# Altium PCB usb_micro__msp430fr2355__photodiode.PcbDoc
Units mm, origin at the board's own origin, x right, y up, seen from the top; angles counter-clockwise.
Board outline 40 x 21 mm, 2 copper layers (Top, Bottom), stack 0 mm thick; 25 components, 16 nets, 135 pads, 49 vias.
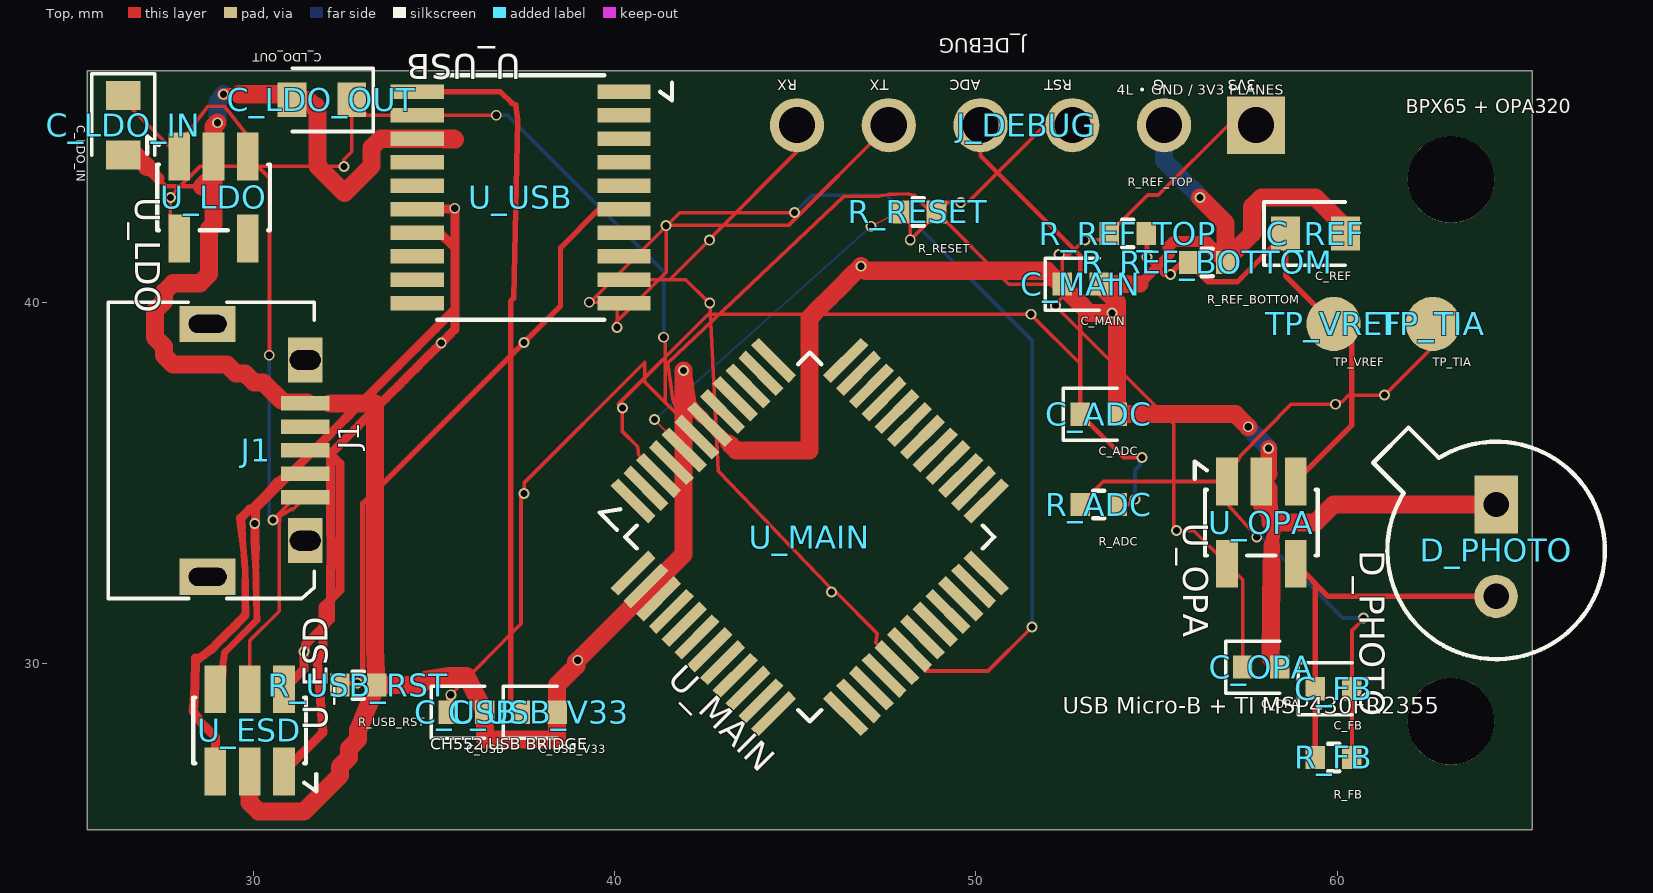
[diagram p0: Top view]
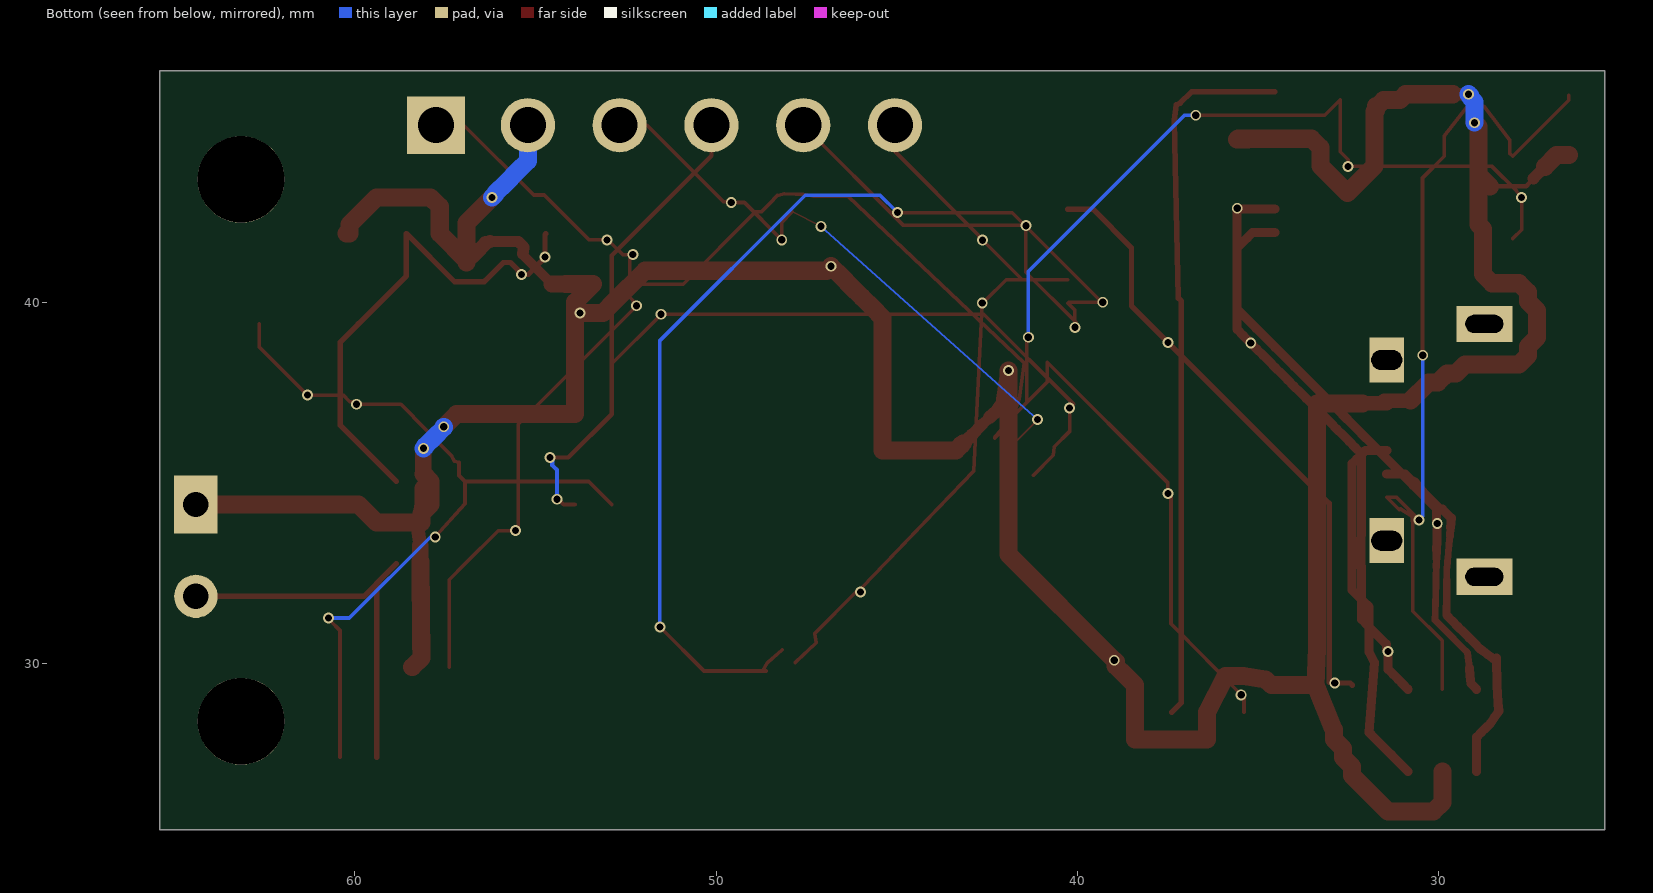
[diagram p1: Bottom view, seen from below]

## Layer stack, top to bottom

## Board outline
25.4,46.4 65.4,46.4 65.4,25.4 25.4,25.4

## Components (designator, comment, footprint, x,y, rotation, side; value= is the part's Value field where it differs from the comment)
C_ADC "" TSCIRCUIT-1.5600x0.6400mm 53.4,36.9 r0 top
C_FB "" TSCIRCUIT-1.5600x0.6400mm 59.9,29.3 r0 top
C_LDO_IN "" TSCIRCUIT-0.9500x2.4500mm 26.4,44.9 r270 top
C_LDO_OUT "" TSCIRCUIT-2.4500x0.9500mm 31.9,45.6 r180 top
C_MAIN "" TSCIRCUIT-1.5600x0.6400mm 52.9,40.5 r0 top
C_OPA "" TSCIRCUIT-1.5600x0.6400mm 57.9,29.9 r0 top
C_REF "" TSCIRCUIT-2.4500x0.9500mm 59.4,41.9 r0 top
C_USB "" TSCIRCUIT-1.5600x0.6400mm 35.9,28.65 r0 top
C_USB_V33 "" TSCIRCUIT-1.5600x0.6400mm 37.9,28.65 r0 top
D_PHOTO "" TSCIRCUIT-1.2000x3.9400mm 64.4,33.23 r270 top
J1 "" TSCIRCUIT-4.1500x8mm 30.037,35.9 r90 top
J_DEBUG "" TSCIRCUIT-14.2000x1.5000mm 51.4,44.9 r180 top
R_ADC "" TSCIRCUIT-1.5600x0.6400mm 53.4,34.4 r0 top
R_FB "" TSCIRCUIT-1.5600x0.6400mm 59.9,27.4 r0 top
R_REF_BOTTOM "" TSCIRCUIT-1.5600x0.6400mm 56.4,41.1 r0 top
R_REF_TOP "" TSCIRCUIT-1.5600x0.6400mm 54.2,41.9 r0 top
R_RESET "" TSCIRCUIT-1.5600x0.6400mm 48.4,42.5 r0 top
R_USB_RST "" TSCIRCUIT-1.5600x0.6400mm 32.9,29.4 r0 top
TP_TIA "" TSCIRCUIT-1.5000x1.5000mm 62.65,39.4 r0 top
TP_VREF "" TSCIRCUIT-1.5000x1.5000mm 59.9,39.4 r0 top
U_ESD "" TSCIRCUIT-2.5000x3.6000mm#1 29.9,28.15 r90 top
U_LDO "" TSCIRCUIT-2.5000x3.6000mm#2 28.9,42.9 r270 top
U_MAIN "" TSCIRCUIT-11.0309x11.0309mm 45.4,33.5 r315 top
U_OPA "" TSCIRCUIT-2.5000x3.6000mm#2 57.9,33.9 r270 top
U_USB "" TSCIRCUIT-7.2000x6.2500mm 37.4,42.9 r180 top

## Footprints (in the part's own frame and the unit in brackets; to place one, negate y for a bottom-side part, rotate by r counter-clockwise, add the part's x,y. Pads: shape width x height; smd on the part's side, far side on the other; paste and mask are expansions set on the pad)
TSCIRCUIT-0.9500x2.4500mm [mm]
  rect 0.8x0.95 smd: 1(-0.825,0) 2(0.825,0)
  silkscreen extent -1.43,-0.87 0.82,0.87
TSCIRCUIT-1.2000x3.9400mm [mm]
  rect 1.6x1.2 hole 0.7: 1(-1.17,0)
  round 1.2 hole 0.7: 2(1.37,0)
  silkscreen extent -3.3,-3.4 3.11,3.01
TSCIRCUIT-1.5000x1.5000mm [mm]
  round 1.5 smd: 1(0,0)
TSCIRCUIT-1.5600x0.6400mm [mm]
  rect 0.54x0.64 smd: 1(-0.51,0) 2(0.51,0)
  silkscreen extent -0.98,-0.72 0.51,0.72
TSCIRCUIT-2.4500x0.9500mm [mm]
  rect 0.8x0.95 smd: 1(-0.825,0) 2(0.825,0)
  silkscreen extent -1.43,-0.87 0.82,0.87
TSCIRCUIT-2.5000x3.6000mm#1 [mm]
  rect 1.325x0.6 smd: 1(-1.137,-0.95) 2(-1.137,0) 3(-1.137,0.95) 4(1.138,0.95) 5(1.138,0) 6(1.138,-0.95)
  silkscreen extent -1.69,-1.84 0.91,1.56
TSCIRCUIT-2.5000x3.6000mm#2 [mm]
  rect 1.325x0.6 smd: 1(-1.137,-0.95) 2(-1.137,0) 3(-1.137,0.95) 4(1.138,0.95) 5(1.138,-0.95)
  silkscreen extent -1.69,-1.84 0.91,1.56
TSCIRCUIT-4.1500x8mm [mm]
  rect 0.4x1.35 smd: 1(-1.301,-1.4) 2(-0.65,-1.4) 3(0,-1.4) 4(0.65,-1.4) 5(1.3,-1.4)
  rect 1.25x0.95 hole 0.55 slot 0.85 at 90 deg: 6(2.5,-1.4) 7(-2.5,-1.4)
  rect 1x1.55 hole 0.5 slot 1.05 at 90 deg: 8(-3.5,1.3) 9(3.5,1.3)
  silkscreen extent -4.1,-1.65 4.1,4.05
TSCIRCUIT-7.2000x6.2500mm [mm]
  rect 1.475x0.4 smd: 1(-2.863,-2.925) 2(-2.863,-2.275) 3(-2.863,-1.625) 4(-2.863,-0.975) 5(-2.863,-0.325) 6(-2.863,0.325) 7(-2.863,0.975) 8(-2.863,1.625) 9(-2.863,2.275) 10(-2.863,2.925) 11(2.862,2.925) 12(2.862,2.275) 13(2.862,1.625) 14(2.862,0.975) 15(2.862,0.325) 16(2.862,-0.325) 17(2.862,-0.975) 18(2.862,-1.625) 19(2.862,-2.275) 20(2.862,-2.925)
  silkscreen extent -4.19,-3.38 2.31,3.38
TSCIRCUIT-11.0309x11.0309mm [mm]
  rect 1.475x0.3 smd: 1(-4.163,-2.75) 2(-4.162,-2.25) 3(-4.163,-1.75) 4(-4.163,-1.25) 5(-4.163,-0.75) 6(-4.162,-0.25) 7(-4.163,0.25) 8(-4.163,0.75) 9(-4.163,1.25) 10(-4.162,1.75) 11(-4.163,2.25) 12(-4.163,2.75) 25(4.162,2.75) 26(4.162,2.25) 27(4.162,1.75) 28(4.162,1.25) 29(4.162,0.75) 30(4.162,0.25) 31(4.162,-0.25) 32(4.162,-0.75) 33(4.162,-1.25) 34(4.162,-1.75) 35(4.162,-2.25) 36(4.162,-2.75)
  rect 0.3x1.475 smd: 13(-2.75,4.162) 14(-2.25,4.163) 15(-1.75,4.162) 16(-1.25,4.162) 17(-0.75,4.162) 18(-0.25,4.163) 19(0.25,4.162) 20(0.75,4.162) 21(1.25,4.162) 22(1.75,4.163) 23(2.25,4.162) 24(2.75,4.162) 37(2.75,-4.162) 38(2.25,-4.162) 39(1.75,-4.162) 40(1.25,-4.162) 41(0.75,-4.162) 42(0.25,-4.162) 43(-0.25,-4.162) 44(-0.75,-4.162) 45(-1.25,-4.162) 46(-1.75,-4.162) 47(-2.25,-4.162) 48(-2.75,-4.162)
  silkscreen extent -4.59,-3.63 3.61,3.61
TSCIRCUIT-14.2000x1.5000mm [mm]
  rect 1.6x1.6 hole 1: 1(-6.35,0)
  round 1.5 hole 1: 2(-3.81,0) 3(-1.27,0) 4(1.27,0) 5(3.81,0) 6(6.35,0)

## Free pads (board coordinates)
  round 2.4 hole 2.4 unplated: NPTH-1(63.15,43.4) NPTH-2(63.15,28.4)

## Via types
v1: diameter 0.3, hole 0.2, Top to Bottom, 49 vias

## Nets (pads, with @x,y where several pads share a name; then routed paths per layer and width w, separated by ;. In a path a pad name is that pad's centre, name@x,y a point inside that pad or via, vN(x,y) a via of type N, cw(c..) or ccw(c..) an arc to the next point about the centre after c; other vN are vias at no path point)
".U_MAIN > .pin5 to .R_RESET > .pin1": J_DEBUG.3 R_RESET.1 U_MAIN.5 | length 16.8
  Top w0.05: v1(41.101,36.75) U_MAIN.5 ; v1(47.1,42.1) R_RESET.1
  Top w0.1: R_RESET.1 48.183,42.207 v1(48.183,41.726) 48.244,41.787 49.216,42.759 v1(49.583,42.759) 49.607,42.783 49.797,42.783 51.915,44.9 J_DEBUG.3
  Bottom w0.05: v1(41.101,36.75) v1(47.1,42.1)
".U_USB > .pin9 to .U_MAIN > .pin32": J_DEBUG.6 U_MAIN.32 U_USB.9 | length 21.8
  Top w0.1: J_DEBUG.6 45.05,44.172 42.735,41.857 42.735,41.83 v1(42.623,41.718) 41.53,40.625 U_USB.9 41.972,40.625 42.531,40.066 42.669,40.066 v1(42.632,39.979) 42.866,35.329 45.956,32.115 45.956,32.028 v1(46.002,31.982) 46.124,31.982 47.274,30.832 47.233,30.573 U_MAIN.32
".U_USB > .pin10 to .U_MAIN > .pin31": J_DEBUG.5 U_MAIN.31 U_USB.10 | length 39.9
  Top w0.1: v1(44.979,42.48) 41.806,42.48 39.313,39.987 v1(39.3,40) 40.238,40 U_USB.10 40.069,39.781 v1(40.069,39.304) 40.038,39.335 40.038,39.445 41.426,40.833 v1(41.426,42.119) 41.432,42.125 41.49,42.125 44.815,42.125 J_DEBUG.5 ; U_MAIN.31 48.573,30.025 48.715,29.797 48.617,29.792 50.337,29.792 51.531,30.986 v1(51.555,31.01)
  Bottom w0.1: v1(44.979,42.48) 44.985,42.486 45.461,42.962 47.534,42.962 51.555,38.941 v1(51.555,31.01)
ADC_IN: C_ADC.1 J_DEBUG.4 R_ADC.2 U_MAIN.3 | length 31.3
  Top w0.1: U_MAIN.3 40.666,35.761 40.638,36 40.217,36.421 v1(40.217,37.073) 40.109,37.181 42.593,39.664 v1(51.522,39.665) 51.577,39.61 51.577,39.606 52.89,38.293 C_ADC.1
  Top w0.12: J_DEBUG.4 50.13,44.052 52.889,41.293 52.889,36.901 C_ADC.1 54.09,35.7 v1(54.6,35.7) ; R_ADC.2 54.221,34.4 54.354,34.534 54.392,34.534 v1(54.406,34.548)
  Bottom w0.12: v1(54.406,34.548) 54.406,35.358 54.539,35.492 54.539,35.639 v1(54.6,35.7)
GND: C_ADC.2 C_LDO_IN.2 C_LDO_OUT.2 C_MAIN.2 C_OPA.2 C_REF.2 C_USB.2 C_USB_V33.2 D_PHOTO.1 J1.5 J_DEBUG.2 R_REF_BOTTOM.2 R_USB_RST.2 U_ESD.2 U_LDO.2 U_MAIN.7 U_OPA.2 U_USB.18 | length 118.9
  Top w0.125: 27.377,43.423 27.575,43.21 28.569,43.21 28.577,43.202
  Top w0.275: 54.539,40.5 54.795,40.756 55.36,41.321 55.36,41.332
  Top w0.3: U_MAIN.7@42.431,36.807 U_MAIN.7
  Top w0.312: 55.36,41.332 55.337,41.4 55.322,41.525 55.478,41.681 55.869,41.681 56.259,41.681
  Top w0.325: 27.057,43.749 27.377,43.423
  Top w0.329: U_MAIN.7 U_MAIN.7@42.922,36.32
  Top w0.35: v1(29.175,45.756) 29.611,45.756 ; 56.259,41.681 56.37,41.64
  Top w0.36: 42.025,37.306 42.228,36.994 U_MAIN.7@42.431,36.807
  Top w0.362: U_MAIN.7@42.922,36.32 U_MAIN.7@43.159,36.102
  Top w0.375: 58.172,34.067 58.244,33.65 58.19,33.266
  Top w0.4: J1.5@30.775,37.275 31.512,37.275 J1.5 J1.5@32.113,37.2 ; U_USB.18 34.563,44.5 U_USB.18@35.275,44.5 ; 56.37,41.64 56.64,41.37 R_REF_BOTTOM.2
  Top w0.45: v1(41.91,38.109) 41.967,37.745 42.025,37.306 ; U_OPA.2@58.103,35.241 v1(58.103,35.955) ; 58.185,32.822 58.19,33.266
  Top w0.475: 43.159,36.102 43.215,36.05 ; 54.163,40.5 54.539,40.5 ; U_OPA.2@58.1,34.484 58.172,34.067
  Top w0.5: C_LDO_IN.2 26.736,44.075 27.057,43.749 ; 28.577,43.202 28.9,43.526 U_LDO.2 ; v1(29.005,44.969) 28.9,44.864 28.9,44.787 28.9,44.412 U_LDO.2 ; 29.611,45.756 30.047,45.756 30.483,45.756 30.919,45.756 C_LDO_OUT.2 31.522,45.6 31.719,45.402 31.741,45.424 31.741,45.309 31.775,45.275 31.775,43.775 32.525,43.025 33.275,43.775 33.275,44.275 33.525,44.525 35.552,44.525 35.577,44.5 35.275,44.5 ; U_ESD.2 29.9,26.15 30.15,25.9 31.4,25.9 32.4,26.9 32.4,27.15 32.65,27.4 32.65,27.65 32.9,27.9 32.9,28.178 32.929,28.206 R_USB_RST.2 ; J1.5@30.775,37.275 30.275,37.775 30.025,37.775 29.775,38.025 29.525,38.025 29.275,38.275 27.775,38.275 27.525,38.525 27.525,38.775 27.275,39.025 27.275,39.775 27.525,40.025 27.525,40.275 27.775,40.525 28.525,40.525 28.775,40.775 28.775,42.025 28.9,42.15 28.9,42.21 28.9,42.667 28.9,43.124 28.9,43.581 U_LDO.2 ; 32.113,37.2 33.365,37.2 33.365,33.368 33.365,32.877 33.365,32.387 33.365,31.897 33.365,31.406 33.365,30.916 33.365,30.425 R_USB_RST.2 ; v1(41.91,38.109) 41.91,33.02 v1(38.981,30.091) 38.939,30.049 38.939,29.931 38.674,29.666 38.41,29.402 38.41,29.026 C_USB_V33.2 38.41,27.9 36.41,27.9 C_USB.2 35.9,29.65 35.4,29.65 34.789,29.561 34.628,29.4 R_USB_RST.2 ; 43.215,36.05 43.358,35.907 43.358,35.9 45.391,35.9 45.391,39.566 45.677,39.852 45.963,40.138 46.249,40.424 46.535,40.71 v1(46.821,40.996) 46.947,40.87 46.972,40.87 51.969,40.87 52.808,40.031 53.137,39.702 53.454,39.702 v1(53.77,39.702) 53.834,39.638 53.834,39.618 53.91,39.542 53.91,39.102 53.91,38.661 53.91,38.221 53.91,37.781 53.91,37.34 C_ADC.2 ; 54.163,40.5 53.786,40.5 C_MAIN.2 53.91,40 C_ADC.2 ; v1(56.2,42.9) 56.91,42.19 R_REF_BOTTOM.2 56.91,41.16 57.65,41.9 57.65,42.65 57.9,42.9 59.4,42.9 60.15,42.15 60.15,41.9 C_REF.2 ; v1(57.539,36.551) 57.19,36.9 C_ADC.2 ; U_OPA.2@58.1,34.484 58.1,34.837 U_OPA.2 ; U_OPA.2@58.103,35.241 U_OPA.2 ; 58.185,32.822 58.181,32.377 58.176,31.932 58.171,31.487 58.166,31.043 58.162,30.598 58.157,30.153 C_OPA.2 ; D_PHOTO.1 59.9,34.4 59.4,33.9 58.15,33.9 58.15,34.15 57.9,34.4 U_OPA.2
  Bottom w0.5: v1(29.005,44.969) 29.005,45.258 29.005,45.548 29.125,45.668 29.125,45.706 v1(29.175,45.756) ; J_DEBUG.2 55.21,44.408 55.21,43.915 55.508,43.617 55.806,43.319 56.105,43.021 56.105,42.995 v1(56.2,42.9) ; v1(57.539,36.551) 57.539,36.526 57.795,36.27 58.051,36.015 58.051,36.007 v1(58.103,35.955)
PD_SUM: C_FB.1 D_PHOTO.2 R_FB.1 U_OPA.4 | length 11.5
  Top w0.15: R_FB.1 C_FB.1 59.39,32.222 U_OPA.4 59.752,31.86 D_PHOTO.2
TIA_OUT: C_FB.2 R_ADC.1 R_FB.2 TP_TIA.1 U_OPA.1 | length 22.2
  Top w0.1: R_ADC.1 53.528,35.037 U_OPA.1 ; v1(57.774,33.505) 56.95,34.417 U_OPA.1 ; R_FB.2 C_FB.2 60.41,30.913 60.684,31.187 60.684,31.213 v1(60.73,31.259) ; TP_TIA.1 62.65,38.769 61.329,37.448 v1(61.311,37.43) 60.319,37.43 60.137,37.248 60.023,37.248 v1(59.95,37.175) 58.725,37.175 57.325,35.75 57.25,35.6 57.118,35.568 57.118,35.205 U_OPA.1
  Bottom w0.1: v1(57.774,33.505) 57.9,33.51 60.151,31.259 v1(60.73,31.259)
USB_BRIDGE_RESET: R_USB_RST.1 U_USB.6 | length 17.2
  Top w0.15: R_USB_RST.1 32.45,29.46 v1(32.875,29.46) 32.921,29.481 33.034,29.481 33.034,34.431 v1(37.491,38.888) 37.518,38.915 38.503,39.9 38.503,41.506 39.572,42.575 U_USB.6
USB_BRIDGE_V33: C_USB_V33.1 U_USB.20 | length 19.8
  Top w0.15: U_USB.20 36.84,45.825 37.154,45.511 37.266,45.462 37.322,45.035 37.204,40.112 37.125,40.033 37.125,28.915 C_USB_V33.1
USB_DM_MCU: U_ESD.4 U_USB.15 | length 17.1
  Top w0.188: 29.176,30.085 29.2,30.3 29.35,30.45 29.5,30.6 29.65,30.75 29.8,30.9 29.95,31.05 30.1,31.2 30.094,31.443 30.089,31.686 30.083,31.929 30.078,32.172 30.072,32.414 30.066,32.657
  Top w0.191: U_ESD.4@29.152,29.87 29.176,30.085
  Top w0.2: 30.061,32.9 30.066,32.657
  Top w0.225: 30.055,33.143 30.061,32.9
  Top w0.25: U_ESD.4 29.104,29.441 29.128,29.656 U_ESD.4@29.152,29.87 ; 30.055,33.143 30.049,33.386 30.044,33.629 v1(30.038,33.872) 30.058,33.891 30.058,34.088 30.058,34.286 30.219,34.448 30.381,34.61 30.543,34.772 30.704,34.933 30.866,35.095 31.028,35.257 31.19,35.418 31.365,35.594 31.541,35.769 31.716,35.945 31.892,36.12 32.067,36.296 32.243,36.471 32.418,36.647 32.594,36.822 32.769,36.998 32.945,37.173 33.12,37.349 33.296,37.524 33.471,37.7 33.647,37.875 33.822,38.051 33.998,38.226 34.173,38.402 34.349,38.577 34.524,38.753 34.7,38.928 34.875,39.104 35.051,39.279 35.226,39.455 35.402,39.63 35.577,39.806 35.577,40.039 35.577,40.272 35.577,40.504 35.577,40.737 35.577,40.97 35.577,41.203 35.577,41.436 35.577,41.669 35.577,41.901 35.577,42.134 35.577,42.367 v1(35.577,42.6) 35.527,42.6 35.502,42.575 35.261,42.575 35.02,42.575 34.779,42.575 U_USB.15
USB_DM_PORT: J1.2 U_ESD.3 | length 10.2
  Top w0.188: 29.713,33.289 29.735,33.049 29.757,32.809 29.779,32.569 29.779,32.322
  Top w0.2: 29.691,33.529 29.713,33.289 ; 29.779,32.075 29.779,32.322
  Top w0.212: 29.779,31.581 29.779,31.828 29.779,32.075
  Top w0.225: 29.669,33.768 29.691,33.529 ; 29.779,31.334 29.779,31.581
  Top w0.238: 29.623,31.178 29.779,31.334
  Top w0.25: U_ESD.3 28.95,27.25 28.95,27.487 28.95,27.724 28.95,27.962 28.82,28.092 28.69,28.221 28.56,28.351 28.449,28.516 28.337,28.681 28.356,28.918 28.374,29.155 28.392,29.392 28.4,30.15 28.447,30.103 28.645,30.251 28.844,30.399 29,30.554 29.156,30.71 29.311,30.866 29.467,31.022 29.623,31.178 ; 29.669,33.768 29.65,34.025 29.9,34.275 29.986,34.298 30.145,34.456 30.304,34.615 30.65,35.025 30.78,35.091 30.939,35.25 31.188,35.25 J1.2
USB_DP_MCU: U_ESD.6 U_USB.14 | length 15.5
  Top w0.25: U_ESD.6 30.988,29.425 31.126,29.563 31.263,29.701 31.401,29.839 31.401,30.085 v1(31.401,30.331) 31.449,30.379 31.449,30.533 31.621,30.705 31.792,30.877 31.964,31.048 32.136,31.22 32.136,31.247 32.136,31.488 32.136,31.728 32.136,31.968 32.136,32.208 32.136,32.448 32.136,32.688 32.15,32.65 32.136,34.368 32.136,34.608 32.136,34.848 32.136,35.088 32.136,35.328 32.136,35.568 32.136,35.808 32.306,35.978 32.476,36.148 32.646,36.318 32.817,36.489 32.987,36.659 33.157,36.829 33.327,36.999 33.498,37.17 33.668,37.34 33.838,37.51 34.008,37.68 34.179,37.851 34.349,38.021 34.519,38.191 34.689,38.361 34.86,38.532 35.03,38.702 v1(35.2,38.872) 35.227,38.899 35.403,39.075 35.58,39.252 35.58,39.502 35.58,39.752 35.58,40.002 35.58,40.252 35.58,40.502 35.58,40.751 35.58,41.001 35.58,41.251 35.58,41.501 35.439,41.643 35.297,41.784 35.156,41.925 34.95,41.925 34.744,41.925 U_USB.14
USB_DP_PORT: J1.3 U_ESD.1 | length 10.3
  Top w0.25: U_ESD.1 31.004,27.167 31.158,27.321 31.312,27.475 31.467,27.629 31.621,27.783 31.775,27.937 31.929,28.092 31.775,30.025 31.929,30.325 31.929,30.573 31.929,30.821 31.929,31.069 31.929,31.317 31.929,31.565 32.084,31.721 32.24,31.876 32.395,32.031 32.395,32.281 32.395,32.531 32.395,32.781 32.395,33.031 32.395,33.281 32.395,33.531 32.395,33.781 32.395,34.031 32.395,34.281 32.395,34.531 32.395,34.781 32.395,35.031 32.395,35.281 32.395,35.531 32.272,35.654 32.149,35.777 32.026,35.9 31.83,35.9 31.634,35.9 J1.3
VBUS5: C_LDO_IN.1 J1.1 U_ESD.5 U_LDO.1 U_LDO.3 | length 23.6
  Top w0.1: C_LDO_IN.1 26.4,45.588 U_LDO.1 28.037,44.124 28.037,44.5 28.75,45.425 29.2,45.425 29.85,44.594 U_LDO.3 30.449,43.439 30.449,38.541 v1(30.439,38.531) ; U_ESD.5 29.9,30.635 30.715,31.45 30.715,33.926 30.732,33.943 30.731,34.073 31.064,34.285 31.09,34.252 J1.1 31.167,34.599 v1(30.543,33.974)
  Bottom w0.1: v1(30.439,38.531) 30.439,34.077 30.477,34.039 v1(30.543,33.974)
VCC_3V3: C_LDO_OUT.1 C_MAIN.1 C_OPA.1 C_USB.1 J_DEBUG.1 R_REF_TOP.1 R_RESET.2 U_LDO.5 U_MAIN.6 U_OPA.5 U_USB.19 | length 75.6
  Top w0.1: U_LDO.5 27.705,42.008 v1(27.704,42.895) 27.854,43.083 27.854,43.091 28.522,43.759 v1(32.51,43.759) 32.502,43.767 32.502,43.943 32.725,44.166 C_LDO_OUT.1 33.15,45.175 U_USB.19 v1(36.724,45.175) ; C_USB.1 35.39,29.053 35.459,29.121 35.459,29.153 v1(35.468,29.132) 37.408,31.102 37.408,34.62 v1(37.494,34.706) 37.494,34.997 40.836,38.34 40.836,37.791 41.833,36.789 42.034,36.584 42.126,36.44 42.155,36.414 42.144,36.391 42.29,36.243 U_MAIN.6 ; v1(41.358,39.032) 41.398,38.992 41.398,38.898 41.398,37.23 41.809,36.82 41.828,36.793 42.046,36.572 42.1,36.439 U_MAIN.6 ; C_OPA.1 57.39,32.322 U_OPA.5 56.034,33.678 v1(55.553,33.678) 55.48,33.751 55.48,33.76 55.48,36.62 v1(52.2,39.9) 52.291,39.991 52.291,40.041 52.39,40.14 C_MAIN.1 ; J_DEBUG.1 56.984,44.9 55.051,42.967 54.757,42.967 R_REF_TOP.1 53.514,41.724 v1(53.023,41.724) 52.946,41.647 52.918,41.647 52.588,41.318 v1(52.305,41.318) 52.367,41.256 52.367,41.24 52.39,41.217 C_MAIN.1 ; U_MAIN.6 42.052,36.559 41.779,36.856 41.615,37.324 41.472,38.321 46.339,42.929 47.313,42.928 47.3,42.928 47.591,42.985 47.8,42.985 48.111,43.002 48.312,42.952 48.508,42.735 48.743,42.5 R_RESET.2 50.91,40.5 C_MAIN.1
  Bottom w0.1: v1(36.724,45.175) 37.035,45.175 41.358,40.852 v1(41.358,39.032)
VREF_0V5: C_REF.1 R_REF_BOTTOM.1 R_REF_TOP.2 TP_VREF.1 U_OPA.3 | length 13.9
  Top w0.15: R_REF_TOP.2 54.736,41.874 v1(54.736,41.251) 54.801,41.186 54.801,41.166 55.2,40.767 v1(55.384,40.767) 55.478,40.861 55.478,40.887 55.692,41.1 R_REF_BOTTOM.1 56.412,40.578 56.412,40.567 57.242,40.567 C_REF.1 58.575,40.725 TP_VREF.1 60.401,38.899 60.401,36.608 60.401,36.588 U_OPA.3
pads on no net: J1.4 J1.6 J1.7 J1.8 J1.9 U_LDO.4 U_MAIN.1 U_MAIN.2 U_MAIN.4 U_MAIN.8 U_MAIN.9 U_MAIN.10 U_MAIN.11 U_MAIN.12 U_MAIN.13 U_MAIN.14 U_MAIN.15 U_MAIN.16 U_MAIN.17 U_MAIN.18 U_MAIN.19 U_MAIN.20 U_MAIN.21 U_MAIN.22 U_MAIN.23 U_MAIN.24 U_MAIN.25 U_MAIN.26 U_MAIN.27 U_MAIN.28 U_MAIN.29 U_MAIN.30 U_MAIN.33 U_MAIN.34 U_MAIN.35 U_MAIN.36 U_MAIN.37 U_MAIN.38 U_MAIN.39 U_MAIN.40 U_MAIN.41 U_MAIN.42 U_MAIN.43 U_MAIN.44 U_MAIN.45 U_MAIN.46 U_MAIN.47 U_MAIN.48 U_USB.1 U_USB.2 U_USB.3 U_USB.4 U_USB.5 U_USB.7 U_USB.8 U_USB.11 U_USB.12 U_USB.13 U_USB.16 U_USB.17

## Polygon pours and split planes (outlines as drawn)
GND on Mid1 (solid): 65.1,46.1 25.7,46.1 25.7,25.7 65.1,25.7 65.1,31.38 65.001,31.259 64.872,31.153 64.725,31.075 64.566,31.026 64.4,31.01 64.234,31.026 64.075,31.075 63.928,31.153 63.799,31.259 63.693,31.388 63.615,31.535 63.566,31.694 63.55,31.86 63.566,32.026 63.615,32.185 63.693,32.332 63.799,32.461 63.928,32.567 64.075,32.645 64.234,32.694 64.4,32.71 64.566,32.694 64.725,32.645 64.872,32.567 65.001,32.461 65.1,32.34 65.1,33.72 65.001,33.599 64.872,33.493 64.725,33.415 64.566,33.366 64.55,33.365 64.55,33.622 64.63,33.646 64.733,33.701 64.824,33.776 64.899,33.867 64.954,33.97 64.988,34.083 65,34.2 65,34.25 65.1,34.25 65.1,34.55 65,34.55 65,34.6 64.988,34.717 64.954,34.83 64.899,34.933 64.824,35.024 64.733,35.099 64.63,35.154 64.55,35.178 64.55,35.435 64.566,35.434 64.725,35.385 64.872,35.307 65.001,35.201 65.1,35.08
VCC_3V3 on Mid2 (solid): 28.974,46.1 25.7,46.1 25.7,25.7 65.1,25.7 65.1,31.38 65.001,31.259 64.872,31.153 64.725,31.075 64.566,31.026 64.4,31.01 64.234,31.026 64.075,31.075 63.928,31.153 63.799,31.259 63.693,31.388 63.615,31.535 63.566,31.694 63.55,31.86 63.566,32.026 63.615,32.185 63.693,32.332 63.799,32.461 63.928,32.567 64.075,32.645 64.234,32.694 64.4,32.71 64.566,32.694 64.725,32.645 64.872,32.567 65.001,32.461 65.1,32.34 65.1,33.72 65.001,33.599 64.872,33.493 64.725,33.415 64.566,33.366 64.4,33.35 64.234,33.366 64.075,33.415 63.928,33.493 63.799,33.599 63.693,33.728 63.615,33.875 63.566,34.034 63.55,34.2 63.55,34.6 63.566,34.766 63.615,34.925 63.693,35.072 63.799,35.201 63.928,35.307 64.075,35.385 64.234,35.434 64.4,35.45 64.566,35.434 64.725,35.385 64.872,35.307 65.001,35.201 65.1,35.08 65.1,46.1 29.376,46.1 29.397,46.089 29.458,46.039 29.508,45.978 29.545,45.909 29.567,45.834 29.575,45.756 29.567,45.678 29.545,45.603 29.508,45.534 29.458,45.473 29.397,45.423 29.328,45.386 29.253,45.364 29.175,45.356 29.097,45.364 29.022,45.386 28.953,45.423 28.892,45.473 28.842,45.534 28.805,45.603 28.783,45.678 28.775,45.756 28.783,45.834 28.805,45.909 28.842,45.978 28.892,46.039 28.953,46.089

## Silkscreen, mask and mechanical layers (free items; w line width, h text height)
Top Overlay:
  text "4L • GND / 3V3 PLANES" at 53.9,45.65 h0.48
  text "BPX65 + OPA320" at 61.9,45.1 h0.65
  text "USB Micro-B + TI MSP430FR2355" at 52.4,28.45 h0.78
  text "CH552 USB BRIDGE" at 34.9,27.5 h0.55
